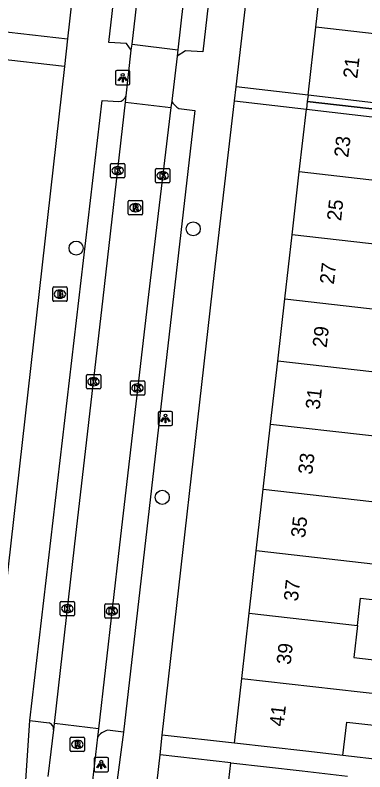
# Model space of a CAD drawing. Extents: x 161696 to 162377, y 380761 to 381673.
# Drawn here: x 162011.6 to 162036, y 381041 to 381093.8 of the extents above; entities that cross this region are included whole.
import ezdxf

# ---------------------------------------------------------------- set-up
doc = ezdxf.new("R2010")
doc.units = 0
for name, color, linetype in [('IMGEO_Boom', 7, 'Continuous'), ('IMGEO_Brandkraan', 7, 'Continuous'), ('IMGEO_Kolk', 7, 'Continuous'), ('IMGEO_Lichtpunt', 7, 'Continuous'), ('IMGEO_Pand', 7, 'Continuous'), ('IMGEO_Pand_nummerreeks', 7, 'Continuous'), ('IMGEO_Pand_overbouw', 7, 'Continuous'), ('IMGEO_Parkeervlak_open', 7, 'Continuous'), ('IMGEO_Rijbaan_lokaal_open', 7, 'Continuous'), ('IMGEO_Rioolput', 7, 'Continuous'), ('IMGEO_Voetpad_open', 7, 'Continuous')]:
    doc.layers.add(name, color=color, linetype=linetype)

msp = doc.modelspace()

# ---------------------------------------------------------------- linework, layer by layer
at = {"layer": 'IMGEO_Boom'}
for centre in [(162024.013, 381078.862), (162015.847, 381077.514), (162021.851, 381060.137)]:
    msp.add_circle(centre, 0.489, dxfattribs=at)
at = {"layer": 'IMGEO_Brandkraan'}
for p, q in [((162014.217, 381073.879), (162014.217, 381074.731)), ((162014.292, 381074.805), (162015.144, 381074.805)), ((162014.705, 381074.585), (162014.73, 381074.585)), ((162015.218, 381074.731), (162015.218, 381073.879)), ((162014.728, 381074.025), (162014.703, 381074.025)), ((162015.144, 381073.805), (162014.292, 381073.805))]:
    msp.add_line(p, q, dxfattribs=at)
for points in [[(162014.217, 381073.879), (162014.217, 381074.731)], [(162014.292, 381074.805), (162015.144, 381074.805)], [(162014.565, 381074.505), (162014.565, 381074.105), (162014.778, 381074.105)], [(162014.796, 381074.505), (162014.565, 381074.505)], [(162015.218, 381074.731), (162015.218, 381073.879)], [(162014.744, 381074.424), (162014.69, 381074.424), (162014.69, 381074.348)], [(162014.69, 381074.348), (162014.743, 381074.348)], [(162014.752, 381074.272), (162014.69, 381074.272), (162014.69, 381074.191)], [(162014.69, 381074.191), (162014.752, 381074.191)], [(162015.144, 381073.805), (162014.292, 381073.805)]]:
    msp.add_lwpolyline(points, dxfattribs=at)
for centre, radius, start, end in [((162014.294, 381074.729), 0.0765, 91.552, 178.448), ((162014.294, 381074.729), 0.0765, 91.552, 178.448), ((162014.8, 381074.36), 0.145, 59.4692, 91.5367), ((162015.142, 381074.729), 0.0765, 1.552, 88.448), ((162015.142, 381074.729), 0.0765, 1.552, 88.448), ((162014.745, 381074.386), 0.0379, 267.8285, 90.9355), ((162014.753, 381074.231), 0.0404, 269.8759, 90.5077), ((162014.784, 381074.356), 0.251, 268.6676, 293.5347), ((162014.825, 381074.407), 0.0922, 285.5137, 58.1501), ((162014.83, 381074.215), 0.105, 301.3115, 78.989), ((162014.294, 381073.881), 0.0765, 181.552, 268.448), ((162014.294, 381073.881), 0.0765, 181.552, 268.448), ((162015.142, 381073.881), 0.0765, 271.552, 358.448), ((162015.142, 381073.881), 0.0765, 271.552, 358.448)]:
    msp.add_arc(centre, radius, start, end, dxfattribs=at)
for centre, major_axis, ratio, start_param, end_param in [((162014.704, 381074.305), (-0.387, 0.002), 0.722429, 4.712389, 7.853982), ((162014.729, 381074.305), (-0.39, 0.002), 0.717154, 1.570796, 4.712389)]:
    msp.add_ellipse(centre, major_axis=major_axis, ratio=ratio, start_param=start_param, end_param=end_param, dxfattribs=at)
at = {"layer": 'IMGEO_Kolk'}
for p, q in [((162018.242, 381082.492), (162018.242, 381083.344)), ((162018.317, 381083.418), (162019.169, 381083.418)), ((162018.73, 381083.198), (162018.755, 381083.198)), ((162019.243, 381083.344), (162019.243, 381082.492)), ((162021.379, 381082.14), (162021.379, 381082.992)), ((162021.454, 381083.066), (162022.306, 381083.066)), ((162022.38, 381082.992), (162022.38, 381082.14)), ((162019.169, 381082.418), (162018.317, 381082.418)), ((162018.753, 381082.638), (162018.728, 381082.638)), ((162021.867, 381082.846), (162021.892, 381082.846)), ((162022.306, 381082.066), (162021.454, 381082.066)), ((162021.89, 381082.286), (162021.865, 381082.286)), ((162016.634, 381068.699), (162017.486, 381068.699)), ((162016.559, 381067.773), (162016.559, 381068.625)), ((162017.047, 381068.479), (162017.072, 381068.479)), ((162017.56, 381068.625), (162017.56, 381067.773)), ((162019.628, 381067.334), (162019.628, 381068.186)), ((162019.703, 381068.26), (162020.555, 381068.26)), ((162020.629, 381068.186), (162020.629, 381067.334)), ((162017.486, 381067.699), (162016.634, 381067.699)), ((162017.07, 381067.919), (162017.045, 381067.919)), ((162020.116, 381068.04), (162020.141, 381068.04)), ((162020.555, 381067.26), (162019.703, 381067.26)), ((162020.139, 381067.48), (162020.114, 381067.48)), ((162014.812, 381052.874), (162015.664, 381052.874)), ((162014.737, 381051.948), (162014.737, 381052.8)), ((162015.225, 381052.654), (162015.25, 381052.654)), ((162015.738, 381052.8), (162015.738, 381051.948)), ((162017.839, 381051.782), (162017.839, 381052.634)), ((162017.914, 381052.708), (162018.766, 381052.708)), ((162018.327, 381052.488), (162018.352, 381052.488)), ((162018.84, 381052.634), (162018.84, 381051.782)), ((162015.664, 381051.874), (162014.812, 381051.874)), ((162015.248, 381052.094), (162015.223, 381052.094)), ((162018.35, 381051.928), (162018.325, 381051.928)), ((162018.766, 381051.708), (162017.914, 381051.708))]:
    msp.add_line(p, q, dxfattribs=at)
for points in [[(162018.242, 381082.492), (162018.242, 381083.344)], [(162018.317, 381083.418), (162019.169, 381083.418)], [(162018.563, 381083.118), (162018.686, 381083.118), (162018.686, 381082.967), (162018.816, 381083.118), (162018.98, 381083.118), (162018.834, 381082.967), (162018.987, 381082.718), (162018.835, 381082.718), (162018.75, 381082.882), (162018.686, 381082.815), (162018.686, 381082.718), (162018.563, 381082.718), (162018.563, 381083.118)], [(162019.243, 381083.344), (162019.243, 381082.492)], [(162021.379, 381082.14), (162021.379, 381082.992)], [(162021.454, 381083.066), (162022.306, 381083.066)], [(162022.38, 381082.992), (162022.38, 381082.14)], [(162019.169, 381082.418), (162018.317, 381082.418)], [(162021.7, 381082.766), (162021.823, 381082.766), (162021.823, 381082.615), (162021.953, 381082.766), (162022.117, 381082.766), (162021.971, 381082.615), (162022.124, 381082.366), (162021.972, 381082.366), (162021.887, 381082.53), (162021.823, 381082.463), (162021.823, 381082.366), (162021.7, 381082.366), (162021.7, 381082.766)], [(162022.306, 381082.066), (162021.454, 381082.066)], [(162016.634, 381068.699), (162017.486, 381068.699)], [(162016.559, 381067.773), (162016.559, 381068.625)], [(162016.88, 381068.399), (162017.003, 381068.399), (162017.003, 381068.248), (162017.133, 381068.399), (162017.297, 381068.399), (162017.151, 381068.248), (162017.304, 381067.999), (162017.152, 381067.999), (162017.067, 381068.163), (162017.003, 381068.096), (162017.003, 381067.999), (162016.88, 381067.999), (162016.88, 381068.399)], [(162017.56, 381068.625), (162017.56, 381067.773)], [(162019.628, 381067.334), (162019.628, 381068.186)], [(162019.703, 381068.26), (162020.555, 381068.26)], [(162020.629, 381068.186), (162020.629, 381067.334)], [(162017.486, 381067.699), (162016.634, 381067.699)], [(162019.949, 381067.96), (162020.072, 381067.96), (162020.072, 381067.809), (162020.202, 381067.96), (162020.366, 381067.96), (162020.22, 381067.809), (162020.373, 381067.56), (162020.221, 381067.56), (162020.136, 381067.724), (162020.072, 381067.657), (162020.072, 381067.56), (162019.949, 381067.56), (162019.949, 381067.96)], [(162020.555, 381067.26), (162019.703, 381067.26)], [(162014.812, 381052.874), (162015.664, 381052.874)], [(162014.737, 381051.948), (162014.737, 381052.8)], [(162015.058, 381052.574), (162015.181, 381052.574), (162015.181, 381052.423), (162015.311, 381052.574), (162015.475, 381052.574), (162015.329, 381052.423), (162015.482, 381052.174), (162015.33, 381052.174), (162015.245, 381052.338), (162015.181, 381052.271), (162015.181, 381052.174), (162015.058, 381052.174), (162015.058, 381052.574)], [(162015.738, 381052.8), (162015.738, 381051.948)], [(162017.839, 381051.782), (162017.839, 381052.634)], [(162017.914, 381052.708), (162018.766, 381052.708)], [(162018.16, 381052.408), (162018.283, 381052.408), (162018.283, 381052.257), (162018.413, 381052.408), (162018.577, 381052.408), (162018.431, 381052.257), (162018.584, 381052.008), (162018.432, 381052.008), (162018.347, 381052.172), (162018.283, 381052.105), (162018.283, 381052.008), (162018.16, 381052.008), (162018.16, 381052.408)], [(162018.84, 381052.634), (162018.84, 381051.782)], [(162015.664, 381051.874), (162014.812, 381051.874)], [(162018.766, 381051.708), (162017.914, 381051.708)]]:
    msp.add_lwpolyline(points, dxfattribs=at)
for centre, start, end in [((162018.319, 381083.342), 91.552, 178.448), ((162018.319, 381083.342), 91.552, 178.448), ((162019.167, 381083.342), 1.552, 88.448), ((162019.167, 381083.342), 1.552, 88.448), ((162021.456, 381082.99), 91.552, 178.448), ((162021.456, 381082.99), 91.552, 178.448), ((162022.304, 381082.99), 1.552, 88.448), ((162022.304, 381082.99), 1.552, 88.448), ((162018.319, 381082.494), 181.552, 268.448), ((162018.319, 381082.494), 181.552, 268.448), ((162019.167, 381082.494), 271.552, 358.448), ((162019.167, 381082.494), 271.552, 358.448), ((162021.456, 381082.142), 181.552, 268.448), ((162021.456, 381082.142), 181.552, 268.448), ((162022.304, 381082.142), 271.552, 358.448), ((162022.304, 381082.142), 271.552, 358.448), ((162016.636, 381068.623), 91.552, 178.448), ((162016.636, 381068.623), 91.552, 178.448), ((162017.484, 381068.623), 1.552, 88.448), ((162017.484, 381068.623), 1.552, 88.448), ((162019.705, 381068.184), 91.552, 178.448), ((162019.705, 381068.184), 91.552, 178.448), ((162020.553, 381068.184), 1.552, 88.448), ((162020.553, 381068.184), 1.552, 88.448), ((162016.636, 381067.775), 181.552, 268.448), ((162016.636, 381067.775), 181.552, 268.448), ((162017.484, 381067.775), 271.552, 358.448), ((162017.484, 381067.775), 271.552, 358.448), ((162019.705, 381067.336), 181.552, 268.448), ((162019.705, 381067.336), 181.552, 268.448), ((162020.553, 381067.336), 271.552, 358.448), ((162020.553, 381067.336), 271.552, 358.448), ((162014.814, 381052.798), 91.552, 178.448), ((162014.814, 381052.798), 91.552, 178.448), ((162015.662, 381052.798), 1.552, 88.448), ((162015.662, 381052.798), 1.552, 88.448), ((162017.916, 381052.632), 91.552, 178.448), ((162017.916, 381052.632), 91.552, 178.448), ((162018.764, 381052.632), 1.552, 88.448), ((162018.764, 381052.632), 1.552, 88.448), ((162014.814, 381051.95), 181.552, 268.448), ((162014.814, 381051.95), 181.552, 268.448), ((162015.662, 381051.95), 271.552, 358.448), ((162015.662, 381051.95), 271.552, 358.448), ((162017.916, 381051.784), 181.552, 268.448), ((162017.916, 381051.784), 181.552, 268.448), ((162018.764, 381051.784), 271.552, 358.448), ((162018.764, 381051.784), 271.552, 358.448)]:
    msp.add_arc(centre, 0.0765, start, end, dxfattribs=at)
for centre, major_axis, ratio, start_param, end_param in [((162018.729, 381082.918), (-0.387, 0.002), 0.722429, 4.712389, 7.853982), ((162018.754, 381082.918), (-0.39, 0.002), 0.717154, 1.570796, 4.712389), ((162021.866, 381082.566), (-0.387, 0.002), 0.722429, 4.712389, 7.853982), ((162021.891, 381082.566), (-0.39, 0.002), 0.717154, 1.570796, 4.712389), ((162017.046, 381068.199), (-0.387, 0.002), 0.722429, 4.712389, 7.853982), ((162017.071, 381068.199), (-0.39, 0.002), 0.717154, 1.570796, 4.712389), ((162020.115, 381067.76), (-0.387, 0.002), 0.722429, 4.712389, 7.853982), ((162020.14, 381067.76), (-0.39, 0.002), 0.717154, 1.570796, 4.712389), ((162015.224, 381052.374), (-0.387, 0.002), 0.722429, 4.712389, 7.853982), ((162015.249, 381052.374), (-0.39, 0.002), 0.717154, 1.570796, 4.712389), ((162018.326, 381052.208), (-0.387, 0.002), 0.722429, 4.712389, 7.853982), ((162018.351, 381052.208), (-0.39, 0.002), 0.717154, 1.570796, 4.712389)]:
    msp.add_ellipse(centre, major_axis=major_axis, ratio=ratio, start_param=start_param, end_param=end_param, dxfattribs=at)
at = {"layer": 'IMGEO_Lichtpunt'}
for p, q in [((162018.592, 381089.802), (162018.592, 381088.995)), ((162018.592, 381089.802), (162018.592, 381088.995)), ((162019.494, 381089.897), (162018.686, 381089.897)), ((162019.494, 381089.897), (162018.686, 381089.897)), ((162019.588, 381088.995), (162019.588, 381089.802)), ((162019.588, 381088.995), (162019.588, 381089.802)), ((162018.686, 381088.901), (162019.494, 381088.901)), ((162018.686, 381088.901), (162019.494, 381088.901)), ((162022.475, 381066.133), (162021.667, 381066.133)), ((162022.475, 381066.133), (162021.667, 381066.133)), ((162021.573, 381066.038), (162021.573, 381065.231)), ((162021.573, 381066.038), (162021.573, 381065.231)), ((162022.569, 381065.231), (162022.569, 381066.038)), ((162022.569, 381065.231), (162022.569, 381066.038)), ((162021.667, 381065.137), (162022.475, 381065.137)), ((162021.667, 381065.137), (162022.475, 381065.137)), ((162017.103, 381041.904), (162017.103, 381041.097)), ((162017.103, 381041.904), (162017.103, 381041.097)), ((162018.005, 381041.999), (162017.197, 381041.999)), ((162018.005, 381041.999), (162017.197, 381041.999)), ((162018.099, 381041.097), (162018.099, 381041.904)), ((162018.099, 381041.097), (162018.099, 381041.904)), ((162017.197, 381041.003), (162018.005, 381041.003)), ((162017.197, 381041.003), (162018.005, 381041.003))]:
    msp.add_line(p, q, dxfattribs=at)
for points in [[(162018.966, 381089.466), (162019.005, 381089.438), (162018.817, 381089.176), (162018.779, 381089.203), (162018.966, 381089.466)], [(162019.068, 381089.418), (162019.115, 381089.418), (162019.115, 381089.096), (162019.068, 381089.096), (162019.068, 381089.418)], [(162019.178, 381089.438), (162019.216, 381089.465), (162019.403, 381089.203), (162019.364, 381089.175), (162019.178, 381089.438)], [(162021.947, 381065.702), (162021.986, 381065.674), (162021.798, 381065.412), (162021.76, 381065.439), (162021.947, 381065.702)], [(162022.049, 381065.654), (162022.096, 381065.654), (162022.096, 381065.332), (162022.049, 381065.332), (162022.049, 381065.654)], [(162022.159, 381065.674), (162022.197, 381065.701), (162022.384, 381065.439), (162022.345, 381065.411), (162022.159, 381065.674)], [(162017.477, 381041.568), (162017.516, 381041.54), (162017.328, 381041.278), (162017.29, 381041.305), (162017.477, 381041.568)], [(162017.579, 381041.52), (162017.626, 381041.52), (162017.626, 381041.198), (162017.579, 381041.198), (162017.579, 381041.52)], [(162017.689, 381041.54), (162017.727, 381041.567), (162017.914, 381041.305), (162017.875, 381041.277), (162017.689, 381041.54)]]:
    msp.add_lwpolyline(points, dxfattribs=at)
for centre in [(162019.091, 381089.6), (162022.072, 381065.836), (162017.602, 381041.702)]:
    msp.add_circle(centre, 0.0994, dxfattribs=at)
for centre, start, end in [((162018.686, 381089.802), 90, 180), ((162018.686, 381089.802), 90, 180), ((162019.494, 381089.802), 0, 90), ((162019.494, 381089.802), 0, 90), ((162018.686, 381088.995), 180, 270), ((162018.686, 381088.995), 180, 270), ((162019.494, 381088.995), 270, 0), ((162019.494, 381088.995), 270, 360), ((162021.667, 381066.038), 90, 180), ((162021.667, 381066.038), 90, 180), ((162022.475, 381066.038), 0, 90), ((162022.475, 381066.038), 0, 90), ((162021.667, 381065.231), 180, 270), ((162021.667, 381065.231), 180, 270), ((162022.475, 381065.231), 270, 0), ((162022.475, 381065.231), 270, 360), ((162017.197, 381041.904), 90, 180), ((162017.197, 381041.904), 90, 180), ((162018.005, 381041.904), 0, 90), ((162018.005, 381041.904), 0, 90), ((162017.197, 381041.097), 180, 270), ((162017.197, 381041.097), 180, 270), ((162018.005, 381041.097), 270, 0), ((162018.005, 381041.097), 270, 360)]:
    msp.add_arc(centre, 0.0946, start, end, dxfattribs=at)
at = {"layer": 'IMGEO_Pand'}
for points in [[(162032.547, 381092.92), (162033.036, 381097.223)], [(162032.008, 381088.174), (162032.547, 381092.92)], [(162045.774, 381091.414), (162032.547, 381092.92)], [(162044.049, 381086.807), (162039.578, 381087.315), (162036.977, 381087.61), (162032.008, 381088.174)], [(162031.4, 381082.824), (162031.897, 381087.196)], [(162031.897, 381087.196), (162036.865, 381086.631), (162039.467, 381086.335)], [(162030.902, 381078.436), (162031.4, 381082.824)], [(162044.547, 381081.331), (162031.4, 381082.824)], [(162030.396, 381073.978), (162030.902, 381078.436)], [(162038.489, 381077.574), (162030.902, 381078.436)], [(162029.902, 381069.631), (162030.396, 381073.978)], [(162030.396, 381073.978), (162043.601, 381072.478)], [(162029.403, 381065.244), (162029.902, 381069.631)], [(162037.469, 381068.772), (162029.902, 381069.631)], [(162028.887, 381060.699), (162029.403, 381065.244)], [(162029.403, 381065.244), (162042.633, 381063.741)], [(162028.399, 381056.401), (162028.887, 381060.699)], [(162028.887, 381060.699), (162036.449, 381059.84)], [(162027.905, 381052.055), (162028.399, 381056.401)], [(162041.61, 381054.9), (162028.399, 381056.401)], [(162035.451, 381051.198), (162035.667, 381053.103), (162041.333, 381052.459), (162041.61, 381054.9)], [(162027.389, 381047.51), (162027.905, 381052.055)], [(162027.905, 381052.055), (162035.451, 381051.198)], [(162035.451, 381051.198), (162035.197, 381048.966), (162040.847, 381048.324), (162040.584, 381046.011)], [(162026.876, 381042.993), (162027.389, 381047.51)], [(162027.389, 381047.51), (162040.584, 381046.011)], [(162034.441, 381042.134), (162034.706, 381044.465), (162040.336, 381043.826)], [(162034.441, 381042.134), (162031.861, 381042.427), (162026.876, 381042.993)], [(162025.936, 381035.586), (162026.624, 381041.617)], [(162026.624, 381041.617), (162031.593, 381041.053), (162034.756, 381040.694)]]:
    msp.add_lwpolyline(points, dxfattribs=at)
at = {"layer": 'IMGEO_Pand_overbouw'}
for points in [[(162031.96, 381087.75), (162031.897, 381087.196), (162036.865, 381086.631), (162039.467, 381086.335), (162039.528, 381086.87)], [(162032.008, 381088.174), (162031.96, 381087.75), (162039.528, 381086.87), (162039.578, 381087.315), (162036.977, 381087.61)]]:
    msp.add_lwpolyline(points, close=True, dxfattribs=at)
at = {"layer": 'IMGEO_Parkeervlak_open'}
for points in [[(162012.631, 381044.57), (162013.964, 381044.409)], [(162019.158, 381043.753), (162018.028, 381043.889)]]:
    msp.add_lwpolyline(points, dxfattribs=at)
for centre, radius, start, end in [((162013.802, 381043.957), 0.48, 357.1758, 70.3154), ((162018.369, 381042.648), 1.287, 105.3557, 143.752)]:
    msp.add_arc(centre, radius, start, end, dxfattribs=at)
at = {"layer": 'IMGEO_Rijbaan_lokaal_open'}
for points in [[(162019.742, 381091.725), (162021.634, 381108.154), (162023.561, 381124.838), (162025.096, 381138.002), (162026.345, 381148.219)], [(162028.651, 381141.53), (162028.633, 381141.398), (162026.457, 381122.199), (162024.918, 381108.886), (162022.934, 381091.333)], [(162019.694, 381091.309), (162019.742, 381091.725)], [(162019.742, 381091.725), (162022.934, 381091.333)], [(162019.333, 381088.124), (162019.694, 381091.309)], [(162022.885, 381090.903), (162022.506, 381087.765)], [(162022.934, 381091.333), (162022.885, 381090.903)], [(162019.283, 381087.682), (162019.333, 381088.124)], [(162022.506, 381087.765), (162022.452, 381087.318)], [(162014.331, 381044.365), (162015.725, 381056.673), (162017.736, 381074.025), (162019.283, 381087.682)], [(162022.452, 381087.318), (162020.88, 381074.29), (162018.867, 381056.828), (162017.398, 381043.995)], [(162019.283, 381087.682), (162022.452, 381087.318)], [(162013.902, 381040.668), (162014.107, 381042.391), (162014.282, 381043.933)], [(162014.282, 381043.933), (162014.331, 381044.365)], [(162017.398, 381043.995), (162014.331, 381044.365)], [(162017.398, 381043.995), (162017.331, 381043.409)], [(162017.331, 381043.409), (162016.985, 381040.382)]]:
    msp.add_lwpolyline(points, dxfattribs=at)
at = {"layer": 'IMGEO_Rioolput'}
for p, q in [((162019.558, 381080.835), (162020.41, 381080.835)), ((162019.483, 381079.909), (162019.483, 381080.761)), ((162019.971, 381080.615), (162019.996, 381080.615)), ((162020.484, 381080.761), (162020.484, 381079.909)), ((162020.41, 381079.835), (162019.558, 381079.835)), ((162019.994, 381080.055), (162019.969, 381080.055)), ((162015.51, 381043.411), (162016.362, 381043.411)), ((162015.435, 381042.485), (162015.435, 381043.337)), ((162015.923, 381043.191), (162015.948, 381043.191)), ((162016.436, 381043.337), (162016.436, 381042.485)), ((162016.362, 381042.411), (162015.51, 381042.411)), ((162015.946, 381042.631), (162015.921, 381042.631))]:
    msp.add_line(p, q, dxfattribs=at)
for points in [[(162019.558, 381080.835), (162020.41, 381080.835)], [(162019.483, 381079.909), (162019.483, 381080.761)], [(162020.072, 381080.533), (162019.82, 381080.535), (162019.82, 381080.135)], [(162019.998, 381080.454), (162019.944, 381080.454), (162019.944, 381080.373)], [(162019.944, 381080.373), (162019.996, 381080.373)], [(162020.484, 381080.761), (162020.484, 381079.909)], [(162020.41, 381079.835), (162019.558, 381079.835)], [(162019.82, 381080.135), (162019.944, 381080.135), (162019.944, 381080.297), (162019.955, 381080.297)], [(162020.002, 381080.268), (162020.073, 381080.135), (162020.213, 381080.135), (162020.148, 381080.261)], [(162015.51, 381043.411), (162016.362, 381043.411)], [(162015.435, 381042.485), (162015.435, 381043.337)], [(162016.024, 381043.109), (162015.772, 381043.111), (162015.772, 381042.711)], [(162015.772, 381042.711), (162015.896, 381042.711), (162015.896, 381042.873), (162015.907, 381042.873)], [(162015.95, 381043.03), (162015.896, 381043.03), (162015.896, 381042.949)], [(162015.896, 381042.949), (162015.948, 381042.949)], [(162015.954, 381042.844), (162016.025, 381042.711), (162016.165, 381042.711), (162016.1, 381042.837)], [(162016.436, 381043.337), (162016.436, 381042.485)], [(162016.362, 381042.411), (162015.51, 381042.411)]]:
    msp.add_lwpolyline(points, dxfattribs=at)
for centre, radius, start, end in [((162019.56, 381080.759), 0.0765, 91.552, 178.448), ((162019.56, 381080.759), 0.0765, 91.552, 178.448), ((162020.408, 381080.759), 0.0765, 1.552, 88.448), ((162020.408, 381080.759), 0.0765, 1.552, 88.448), ((162019.98, 381080.562), 0.19, 274.7715, 282.9687), ((162020.004, 381080.358), 0.0964, 77.0061, 93.1865), ((162020.018, 381080.415), 0.0378, 276.6634, 79.6772), ((162020.071, 381080.423), 0.109, 350.3612, 89.416), ((162020.069, 381080.423), 0.112, 277.5842, 350.9817), ((162020.053, 381080.208), 0.108, 29.5134, 73.7905), ((162019.56, 381079.911), 0.0765, 181.552, 268.448), ((162019.56, 381079.911), 0.0765, 181.552, 268.448), ((162019.954, 381080.244), 0.0533, 26.0293, 88.6989), ((162020.408, 381079.911), 0.0765, 271.552, 358.448), ((162020.408, 381079.911), 0.0765, 271.552, 358.448), ((162015.512, 381043.335), 0.0765, 91.552, 178.448), ((162015.512, 381043.335), 0.0765, 91.552, 178.448), ((162016.36, 381043.335), 0.0765, 1.552, 88.448), ((162016.36, 381043.335), 0.0765, 1.552, 88.448), ((162015.906, 381042.82), 0.0533, 26.0293, 88.6989), ((162015.932, 381043.138), 0.19, 274.7715, 282.9687), ((162015.956, 381042.934), 0.0964, 77.0061, 93.1865), ((162015.97, 381042.991), 0.0378, 276.6634, 79.6772), ((162016.023, 381042.999), 0.109, 350.3612, 89.416), ((162016.021, 381042.999), 0.112, 277.5842, 350.9817), ((162016.005, 381042.784), 0.108, 29.5134, 73.7905), ((162015.512, 381042.487), 0.0765, 181.552, 268.448), ((162015.512, 381042.487), 0.0765, 181.552, 268.448), ((162016.36, 381042.487), 0.0765, 271.552, 358.448), ((162016.36, 381042.487), 0.0765, 271.552, 358.448)]:
    msp.add_arc(centre, radius, start, end, dxfattribs=at)
for centre, major_axis, ratio, start_param, end_param in [((162019.97, 381080.335), (-0.387, 0.002), 0.722429, 4.712389, 7.853982), ((162019.995, 381080.335), (-0.39, 0.002), 0.717154, 1.570796, 4.712389), ((162015.922, 381042.911), (-0.387, 0.002), 0.722429, 4.712389, 7.853982), ((162015.947, 381042.911), (-0.39, 0.002), 0.717154, 1.570796, 4.712389)]:
    msp.add_ellipse(centre, major_axis=major_axis, ratio=ratio, start_param=start_param, end_param=end_param, dxfattribs=at)
at = {"layer": 'IMGEO_Voetpad_open'}
for points in [[(162027.003, 381088.756), (162032.093, 381132.546), (162033.856, 381148.586)], [(162019.694, 381091.309), (162019.352, 381091.773), (162018.133, 381091.846), (162024.595, 381148.112), (162025.853, 381147.926)], [(162020.89, 381142.109), (162015.25, 381092.109)], [(162029.151, 381141.009), (162030.343, 381140.871), (162024.673, 381091.207), (162023.479, 381091.266), (162022.885, 381090.903)], [(162010.343, 381092.663), (162015.25, 381092.109)], [(162015.25, 381092.109), (162015.033, 381090.181)], [(162015.033, 381090.181), (162010.119, 381090.735)], [(162015.033, 381090.181), (162009.512, 381041.24)], [(162026.889, 381087.778), (162027.003, 381088.756)], [(162032.008, 381088.174), (162027.003, 381088.756)], [(162012.631, 381044.57), (162017.652, 381087.808), (162018.82, 381087.735)], [(162021.85, 381043.562), (162025.499, 381075.815), (162026.889, 381087.778)], [(162026.889, 381087.778), (162031.897, 381087.196)], [(162023.01, 381087.254), (162024.115, 381087.105), (162019.158, 381043.753)], [(162012.34, 381040.393), (162012.631, 381044.57)], [(162019.158, 381043.753), (162018.613, 381039.74)], [(162021.693, 381042.175), (162021.85, 381043.562)], [(162026.876, 381042.993), (162021.85, 381043.562)], [(162015.99, 380993.672), (162016.694, 381000), (162018.038, 381009.86), (162021.693, 381042.175)], [(162026.624, 381041.617), (162021.693, 381042.175)], [(162040.068, 381041.477), (162034.441, 381042.134)]]:
    msp.add_lwpolyline(points, dxfattribs=at)
for centre, radius, start, end in [((162018.783, 381088.316), 0.582, 273.6013, 340.7436), ((162023.622, 381088.361), 1.265, 208.1234, 241.0863)]:
    msp.add_arc(centre, radius, start, end, dxfattribs=at)

# ---------------------------------------------------------------- texts
at = {"layer": 'IMGEO_Pand_nummerreeks'}
for s, rotation, p in [('21', 83.5203, (162035.438, 381089.307)), ('23', 83.5196, (162034.812, 381083.795)), ('25', 83.5196, (162034.31, 381079.374)), ('27', 83.5201, (162033.808, 381074.954)), ('29', 83.5196, (162033.306, 381070.534)), ('31', 83.5201, (162032.816, 381066.225)), ('33', 83.5196, (162032.302, 381061.693)), ('35', 83.5196, (162031.8, 381057.273)), ('37', 83.5196, (162031.298, 381052.852)), ('39', 83.5196, (162030.796, 381048.432)), ('41', 83.5201, (162030.306, 381044.124))]:
    msp.add_text(s, height=1, rotation=rotation, dxfattribs=at).set_placement(p)

doc.saveas('drawing.dxf')
